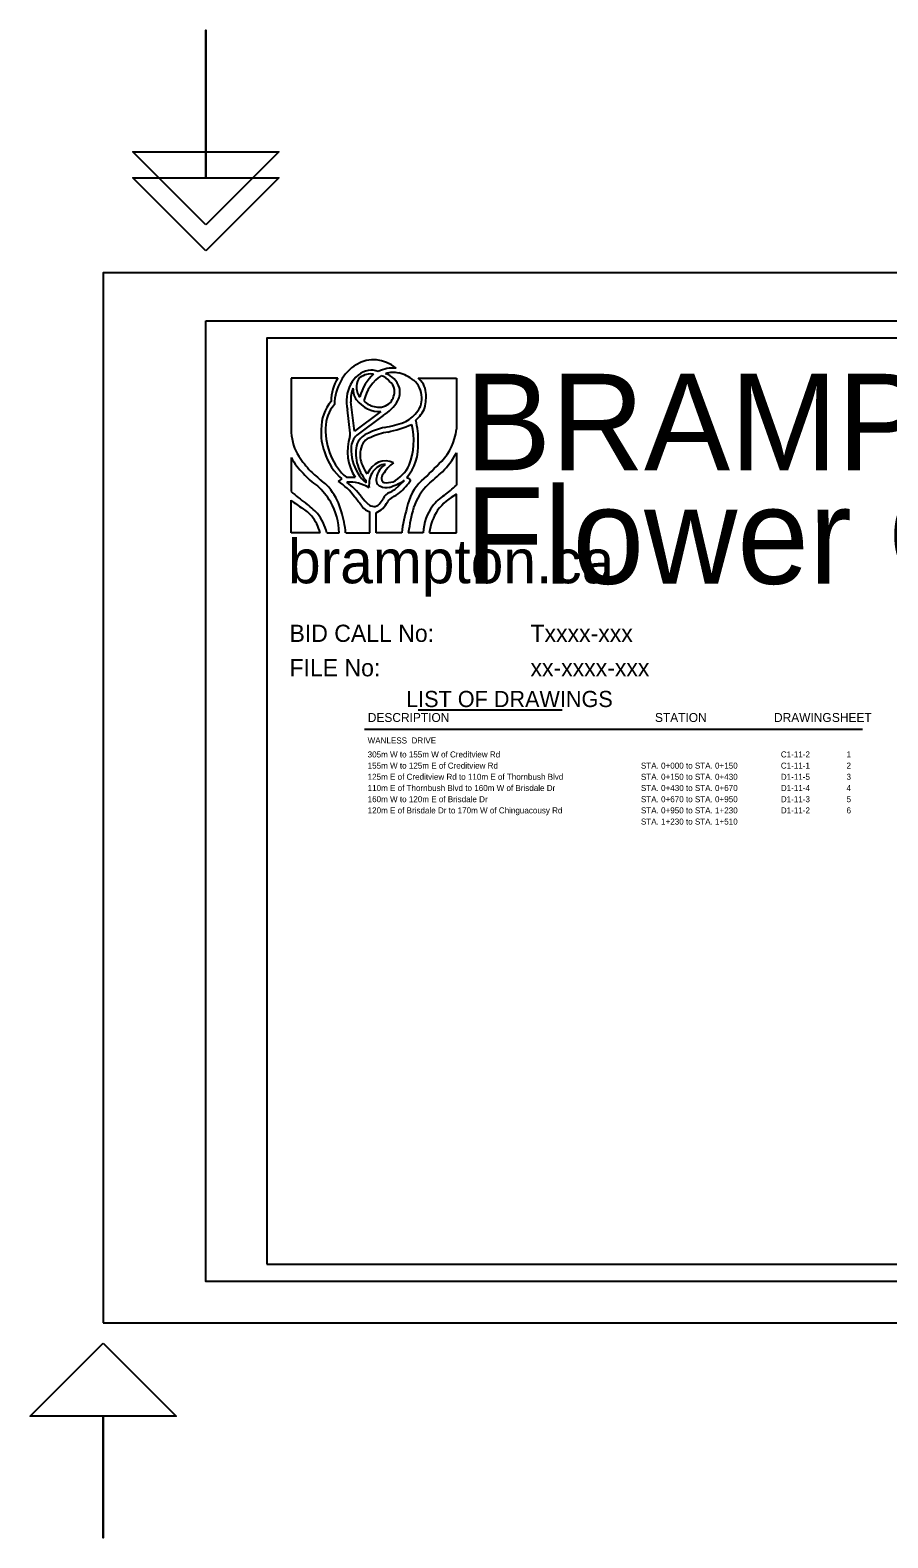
# Model space of a CAD drawing. Extents: x 589136 to 589858, y 4822787 to 4823225.
# Drawn here: x 589136 to 589385.1, y 4822787.2 to 4823225.1 of the extents above; entities that cross this region are included whole.
import ezdxf

# ---------------------------------------------------------------- set-up
doc = ezdxf.new("R2010")
doc.units = 0
for name, color, linetype in [('-PRINT FULLSIZE', 7, 'Continuous'), ('-PRINT HALFSIZE', 7, 'Continuous'), ('ENG_BORDER', 7, 'Continuous'), ('ENG_LOGO', 7, 'Continuous'), ('ENG_TITLEBLOCK', 7, 'Continuous'), ('ENG_TX_LOGO', 7, 'Continuous'), ('ENG_TX_TITLEBLOCK', 7, 'Continuous'), ('ENG_WK_MISC-1', 7, 'Continuous')]:
    doc.layers.add(name, color=color, linetype=linetype)

msp = doc.modelspace()

# ---------------------------------------------------------------- linework, layer by layer
at = {"layer": '-PRINT FULLSIZE'}
msp.add_lwpolyline([(589157.2, 4822849.64), (589604.23, 4822849.64), (589604.23, 4823154.64), (589157.2, 4823154.64)], close=True, dxfattribs=at)
at = {"layer": '-PRINT HALFSIZE'}
msp.add_lwpolyline([(589187, 4823140.63), (589595.92, 4823140.63), (589595.92, 4822861.63), (589187, 4822861.63)], close=True, dxfattribs=at)
at = {"layer": 'ENG_BORDER'}
msp.add_lwpolyline([(589204.72, 4822866.63), (589590.92, 4822866.63), (589590.92, 4823135.63), (589204.72, 4823135.63)], close=True, dxfattribs=at)
at = {"layer": 'ENG_LOGO'}
for p, q in [((589225.35, 4823124.01), (589211.83, 4823124.01)), ((589211.83, 4823124.01), (589211.83, 4823108.19)), ((589248.65, 4823124.01), (589259.81, 4823124.01)), ((589259.81, 4823124.01), (589259.81, 4823109.16)), ((589230.24, 4823108.62), (589229.18, 4823117.15)), ((589228.97, 4823108.07), (589228.14, 4823114.78)), ((589237.89, 4823114.36), (589230.24, 4823108.62)), ((589238.52, 4823113.17), (589230.86, 4823107.43)), ((589259.81, 4823102.36), (589259.81, 4823092.89)), ((589211.83, 4823100.93), (589211.83, 4823091.11)), ((589227.83, 4823095.23), (589230.42, 4823095.23)), ((589233.57, 4823093.58), (589233.57, 4823094.26)), ((589241.94, 4823091.72), (589244.73, 4823094.34)), ((589259.81, 4823079.1), (589259.81, 4823090.31)), ((589211.83, 4823079.1), (589211.83, 4823088.54)), ((589234.63, 4823079.1), (589234.63, 4823085.2)), ((589236.49, 4823079.1), (589236.49, 4823084.94)), ((589220.23, 4823079.1), (589211.83, 4823079.1)), ((589222.16, 4823079.1), (589225.77, 4823079.1)), ((589227.64, 4823079.1), (589234.63, 4823079.1)), ((589243.93, 4823079.1), (589236.49, 4823079.1)), ((589250.15, 4823079.1), (589245.83, 4823079.1)), ((589251.94, 4823079.1), (589259.81, 4823079.1))]:
    msp.add_line(p, q, dxfattribs=at)
for centre, major_axis, start_param, end_param in [((589235.77, 4823115.7), (0, 13.65), 5.678233, 7.807497), ((589232.73, 4823117.24), (0, 11.11), 0.915828, 1.568717), ((589235.5, 4823117.27), (0, -9.13), 3.318986, 4.976585), ((589233.33, 4823121.8), (0, 3.01), 0.666047, 1.576027), ((589242.28, 4823114.45), (0, 13.23), 0.628774, 1.255965), ((589234.84, 4823118.49), (0, 6.75), 6.118882, 6.855525), ((589242.74, 4823113.88), (0, 12.27), 0.484278, 1.276713), ((589235.1, 4823119.28), (0, 7.07), 5.937042, 6.443816), ((589241.44, 4823113.47), (0, 13.49), 6.209925, 6.677582), ((589236.55, 4823118.34), (0, 6.61), 5.514665, 6.02559), ((589241.51, 4823115.43), (0, 10.25), 6.104016, 6.552384), ((589237.94, 4823118.54), (0, 6.94), 5.100192, 6.058655), ((589240.64, 4823110.91), (0, 14.89), 5.705811, 6.088794), ((589246.07, 4823118.97), (0, 5.91), 4.858966, 5.733736), ((589235.25, 4823117.91), (0, 7.29), 1.119551, 1.674398), ((589237, 4823121.49), (0, -8.66), 4.758696, 4.974719), ((589233.91, 4823121.23), (0, 3.73), 1.423327, 2.376918), ((589238.7, 4823119.88), (0, 3.8), 4.934552, 5.720905), ((589237.8, 4823120.38), (0, -4.8), 0.785512, 1.640949), ((589238.87, 4823120.19), (0, 5.4), 4.195874, 4.894963), ((589244.44, 4823118.16), (0, 6.34), 4.747453, 5.681752), ((589240.17, 4823118.73), (0, -12.94), 1.316711, 1.656268), ((589229.95, 4823109.13), (0, 11.26), 0.764321, 1.571722), ((589229.67, 4823109.4), (0, 9.4), 0.74139, 1.563754), ((589232.59, 4823120.12), (0, -3.22), 4.989814, 5.515803), ((589237.32, 4823125.05), (0, -10.72), 5.455385, 6.346676), ((589236.86, 4823122.77), (0, -7.12), 5.558935, 6.198642), ((589237.32, 4823121.82), (0, -6.26), 6.098575, 6.969537), ((589233.31, 4823125.7), (0, -13.98), 0.460861, 0.945922), ((589242.26, 4823120.77), (0, -11.33), 0.654188, 1.084874), ((589245.62, 4823117.91), (0, 4.94), 3.823835, 4.807307), ((589227.38, 4823114.65), (0, -0.92), 1.717889, 1.834992), ((589230.14, 4823174.25), (0, -65.38), 0.161819, 0.267812), ((589241.59, 4823121.29), (0, -10.72), 0.344201, 0.831804), ((589229.25, 4823105.59), (0, -23.28), 1.565289, 1.83996), ((589222.42, 4823109.12), (0, -12.69), 4.785712, 5.370532), ((589231.52, 4823108.11), (0, 13.18), 1.493845, 2.002346), ((589236.17, 4823109.21), (0, 17.16), 1.555738, 2.522651), ((589237.93, 4823102.71), (0, 11.67), 1.184297, 2.265825), ((589227.45, 4823107.8), (0, 1.84), 4.32589, 4.859481), ((589233.24, 4823103.59), (0, 4.78), 0.63706, 1.540523), ((589235.89, 4823101.52), (0, 6.84), 0.28455, 1.028854), ((589235.63, 4823102.48), (0, 4.4), 0.179588, 1.425103), ((589245.3, 4823073.65), (0, 36.86), 0.207106, 0.364997), ((589243.21, 4823081.6), (0, 27.06), 0.147367, 0.372097), ((589232.31, 4823158.82), (0, -51.25), 0.177455, 0.344982), ((589233.57, 4823105.8), (0, 16.54), 4.273394, 5.005808), ((589247.22, 4823111.42), (0, -15.21), 0.712478, 1.421371), ((589234.47, 4823108.28), (0, -16.51), 5.06368, 5.674398), ((589239.81, 4823103.41), (0, -12.63), 4.68622, 4.981796), ((589238.62, 4823102.11), (0, 9.58), 1.258524, 1.853874), ((589236.86, 4823101.67), (0, 6), 1.326911, 2.090694), ((589237.44, 4823104.74), (0, -13.52), 0.78097, 1.623824), ((589243.82, 4823114.34), (0, -22.55), 0.682687, 1.010528), ((589225.63, 4823111.74), (0, -19.71), 5.292666, 5.605077), ((589234.11, 4823119.88), (0, -30.32), 5.369755, 5.566262), ((589239.67, 4823103.85), (0, -12.6), 5.019488, 5.665896), ((589240.2, 4823102.65), (0, -11.54), 4.995413, 5.526463), ((589239.19, 4823102.25), (0, -8.75), 5.131028, 5.477302), ((589239.21, 4823092.85), (0, 7.16), 5.87892, 7.368381), ((589239.32, 4823093.11), (0, -5.87), 3.173377, 4.865507), ((589241.51, 4823093.55), (0, 6.11), 0.477744, 1.324571), ((589246.62, 4823089.19), (0, 11.89), 0.532188, 0.957727), ((589237.42, 4823105.13), (0, -12.17), 0.401305, 1.020747), ((589119.3, 4823290.86), (0, -250.88), 0.669806, 0.705808), ((589231.54, 4823117.4), (0, -28.62), 5.537119, 5.75381), ((589540.12, 4823608.56), (0, -640.49), 5.63745, 5.644913), ((589216.08, 4823084.19), (0, 11.36), 5.416876, 5.78378), ((589228.56, 4823088.52), (0, 6.66), 0.365522, 0.597805), ((589217.46, 4823075.85), (0, 20.52), 5.439641, 5.800947), ((589228.67, 4823078.25), (0, 15.58), 5.823202, 6.334077), ((589213.72, 4823068.09), (0, 30.87), 5.482733, 5.697338), ((589238.11, 4823094.5), (0, 1.94), 1.287529, 2.899642), ((589239.21, 4823094.97), (0, 1.37), 0.693494, 2.795441), ((589239.45, 4823103.55), (0, -9.89), 6.206413, 6.519617), ((589235.13, 4823116.23), (0, -24.71), 0.25264, 0.48256), ((589229.69, 4823111.66), (0, -26.53), 0.664019, 0.865631), ((589243.99, 4823089.78), (0, 5.62), 5.695616, 5.978543), ((589256.8, 4823083.08), (0, 13.98), 0.6523, 1.336939), ((589188.67, 4823198.46), (0, -129.38), 0.619451, 0.667551), ((589235.09, 4823126.96), (0, -45.35), 5.623762, 5.757196), ((589209.9, 4823076.87), (0, 19.5), 5.320654, 5.659535), ((589213.14, 4823080.22), (0, 16.62), 5.018027, 5.462353), ((589175.12, 4823025.87), (0, 91.59), 5.441321, 5.480214), ((589238.75, 4823095.73), (0, -9.89), 5.382989, 5.704264), ((589225.75, 4823100.14), (0, -18.89), 0.828888, 0.938456), ((589239.46, 4823097.72), (0, -5.5), 5.896411, 6.466099), ((589240.93, 4823087.69), (0, 3.16), 0.214109, 1.153309), ((589242.97, 4823084.73), (0, 5.11), 0.422403, 0.821661), ((589235.8, 4823104.04), (0, -14.35), 0.390063, 0.537232), ((589235.09, 4823106.3), (0, -18.42), 0.408149, 0.566756), ((589261.25, 4823079.11), (0, 18.17), 0.690534, 1.157714), ((589260.71, 4823078.88), (0, 12.27), 0.445246, 0.869293), ((589266.68, 4823071.82), (0, 20.23), 0.417687, 0.818457), ((589222.95, 4823151.57), (0, -73.36), 0.573803, 0.643743), ((589229.34, 4823119.42), (0, -37.3), 5.687848, 5.809574), ((589210.43, 4823075.14), (0, 12.41), 5.497917, 5.817483), ((589204.83, 4823065.65), (0, 25.81), 5.540505, 5.738863), ((589210.31, 4823074.58), (0, 14.87), 5.021624, 5.458474), ((589210.76, 4823078.1), (0, 17.97), 4.76812, 5.296774), ((589208.04, 4823076.77), (0, 23.52), 4.811691, 5.079969), ((589235.61, 4823090.26), (0, -5.19), 5.423199, 6.055208), ((589235.86, 4823089.77), (0, -3.03), 5.581796, 6.941571), ((589234.55, 4823091.84), (0, -7.29), 0.32402, 1.048968), ((589273.18, 4823074.31), (0, 35.26), 1.223572, 1.434629), ((589294.78, 4823068.73), (0, 59.37), 1.268607, 1.395258), ((589260.4, 4823078.48), (0, 12.26), 0.824174, 1.519908), ((589264.43, 4823076.5), (0, 15.15), 0.923116, 1.39853), ((589210.03, 4823074.97), (0, 12.87), 5.039091, 5.480629)]:
    msp.add_ellipse(centre, major_axis=major_axis, ratio=0.837209, start_param=start_param, end_param=end_param, dxfattribs=at)
at = {"layer": 'ENG_TITLEBLOCK'}
for p, q in [((589248.71, 4823027.66), (589290.49, 4823027.66)), ((589233.09, 4823022.1), (589377.78, 4823022.1))]:
    msp.add_line(p, q, dxfattribs=at)
at = {"layer": 'ENG_WK_MISC-1'}
for points in [[(589187, 4823168.53), (589165.79, 4823189.74), (589187, 4823189.74), (589187, 4823225.1), (589187, 4823189.74), (589208.21, 4823189.74)], [(589187, 4823161.03), (589165.79, 4823182.24), (589187, 4823182.24), (589187, 4823217.6), (589187, 4823182.24), (589208.21, 4823182.24)], [(589157.2, 4822843.75), (589178.42, 4822822.53), (589157.2, 4822822.53), (589157.2, 4822787.18), (589157.2, 4822822.53), (589135.99, 4822822.53)]]:
    msp.add_lwpolyline(points, close=True, dxfattribs=at)

# ---------------------------------------------------------------- texts
at = {"layer": 'ENG_TX_LOGO'}
msp.add_text('brampton.ca', height=12.75, rotation=360, dxfattribs=at).set_placement((589210.89, 4823064.44))
at = {"layer": 'ENG_TX_TITLEBLOCK'}
for s, height, p in [('BRAMPTON', 28, (589262.32, 4823097.28)), ('Flower City', 28, (589262.32, 4823064.28)), ('BID CALL No: ', 5, (589211.32, 4823047.41)), ('Txxxx-xxx', 5, (589281.32, 4823047.41)), ('FILE No: ', 5, (589211.32, 4823037.41)), ('xx-xxxx-xxx', 5, (589281.32, 4823037.41)), ('LIST OF DRAWINGS', 4.698, (589245.19, 4823028.48)), ('DESCRIPTION', 2.592, (589234.07, 4823024.16)), ('STATION', 2.592, (589317.48, 4823024.16)), ('DRAWING', 2.592, (589352.05, 4823024.16)), ('SHEET', 2.592, (589368.87, 4823024.16)), ('WANLESS  DRIVE', 1.75, (589234.02, 4823017.91)), ('305m W to 155m W of Creditview Rd', 1.75, (589234.02, 4823013.85)), ('C1-11-2', 1.75, (589354.04, 4823013.85)), ('1', 1.75, (589373.12, 4823013.85)), ('155m W to 125m E of Creditview Rd', 1.75, (589234.02, 4823010.6)), ('STA. 0+000 to STA. 0+150', 1.75, (589313.4, 4823010.6)), ('C1-11-1', 1.75, (589354.04, 4823010.6)), ('2', 1.75, (589373.12, 4823010.6)), ('125m E of Creditview Rd to 110m E of Thornbush Blvd', 1.75, (589234.02, 4823007.35)), ('110m E of Thornbush Blvd to 160m W of Brisdale Dr', 1.75, (589234.02, 4823004.1)), ('STA. 0+150 to STA. 0+430', 1.75, (589313.4, 4823007.35)), ('STA. 0+430 to STA. 0+670', 1.75, (589313.4, 4823004.1)), ('D1-11-5', 1.75, (589354.04, 4823007.35)), ('D1-11-4', 1.75, (589354.04, 4823004.1)), ('4', 1.75, (589373.12, 4823004.1)), ('3', 1.75, (589373.12, 4823007.35)), ('160m W to 120m E of Brisdale Dr', 1.75, (589234.02, 4823000.85)), ('STA. 0+670 to STA. 0+950', 1.75, (589313.4, 4823000.85)), ('D1-11-3', 1.75, (589354.04, 4823000.85)), ('5', 1.75, (589373.12, 4823000.85)), ('120m E of Brisdale Dr to 170m W of Chinguacousy Rd', 1.75, (589234.02, 4822997.6)), ('STA. 0+950 to STA. 1+230', 1.75, (589313.4, 4822997.6)), ('D1-11-2', 1.75, (589354.04, 4822997.6)), ('6', 1.75, (589373.12, 4822997.6)), ('STA. 1+230 to STA. 1+510', 1.75, (589313.4, 4822994.35))]:
    msp.add_text(s, height=height, dxfattribs=at).set_placement(p)

doc.saveas('drawing.dxf')
